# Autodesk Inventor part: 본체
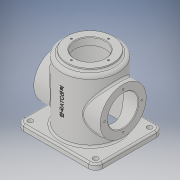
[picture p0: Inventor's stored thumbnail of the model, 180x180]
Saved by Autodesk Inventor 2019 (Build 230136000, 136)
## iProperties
Created: 2020-12
Part Number: 본체
Material: 일반
Document SubType Name: Modeling
Designer: jun-1-19
Density: 1 g/cm^3
Appearance: 기본값
Mass: 457.557 g
Surface Area: 1067.12 cm^2
Volume: 457.557 cm^3
Author: jun-1-19
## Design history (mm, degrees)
sketch "스케치1"
  geometry: L1 (70, -60)-(-70, -60); L2 (-70, -60)-(-70, 60); L3 (-70, 60)-(70, 60); L4 (70, 60)-(70, -60); L5 (70, -60)-(-70, 60); L6 (-70, -60)-(70, 60); 1 further point
  constraints: 12 end point, 2 midpoint, 2 parallel, 1 horizontal, 1 perpendicular
  dimensions: "d0" = 140 distance of L2.end L3.end; "d1" = 120 distance of L1.end L2.end
extrude "돌출1" new body sketch "스케치1" distance "d2" = 10; taper "d3" = 0 deg
sketch "스케치2"
  geometry: C1 r 50 at (0, 0); 1 further point
  constraints: 1 centre point, 1 coincident
  dimensions: "d4" = 100 diameter of C1
extrude "돌출2" join sketch "스케치2" distance "d5" = 110; taper "d6" = 0 deg
sketch "스케치4"
  geometry: C1 r 41 at (0, 0); 1 further point
  constraints: 1 centre point, 1 coincident
  dimensions: "d8" = 82 diameter of C1
extrude "돌출3" join sketch "스케치4" distance "d9" = 5; taper "d10" = 0 deg
sketch "스케치5"
  geometry: 3 further points
  constraints: 2 coincident
hole "구멍1" sketch "스케치5" at (0, 0) diameter "d11" = 54; stored, may be unused: countersink angle "d15" = 90 deg, drill point angle "d17" = 0 deg; dims "d12" = 18, "d13" = 84, "d14" = 112, "d16" = 23
node "작업 평면4"
sketch "스케치6"
  geometry: L1 (0, -60)-(0, 60) reference; C1 r 41 at (60, 0); 2 further points
  constraints: 1 centre point, 1 horizontal alignment, 1 midpoint
  dimensions: "d19" = 82 diameter of C1; "d20" = 60 distance from line of L1 C1.centre
extrude "돌출4" join sketch "스케치6" stored distance "d21" = 5; taper "d22" = 0 deg
sketch "스케치7"
  geometry: C1 r 41 at (0, 0) reference; 2 further points
  constraints: 1 coincident
hole "구멍2" sketch "스케치7" at (0, 0) diameter "d23" = 54; stored, may be unused: countersink angle "d27" = 90 deg, drill point angle "d29" = 0 deg; dims "d24" = 18, "d25" = 84, "d26" = 112, "d28" = 23
fillet "모깎기1" dims "d30" = 12
sketch "스케치8"
  geometry: A1 r 12 centre (58, -48) between (58, -60) and (70, -48) reference; 2 further points
  constraints: 1 coincident
hole "구멍3" sketch "스케치8" at (58, -48) diameter "d31" = 9; stored, may be unused: countersink angle "d35" = 90 deg, drill point angle "d37" = 0 deg; dims "d32" = 18, "d33" = 84, "d34" = 112, "d36" = 23
fillet "모깎기2" dims "d38" = 3
sketch "스케치9"
  geometry: 2 further points
  constraints: 1 vertical alignment
  dimensions: "d39" = 33 distance of point (0, 0) point (0, 33)
hole "구멍4" sketch "스케치9" at (0, 33) diameter "d40" = 3.242; stored, may be unused: countersink angle "d44" = 90 deg, drill point angle "d46" = 118 deg; dims "d41" = 8, "d42" = 84, "d43" = 112, "d45" = 10
sketch "스케치10"
  geometry: L1 (48, -60)-(-48, -60) reference; C1 r 41 at (0, 0) reference; 3 further points
  constraints: 1 midpoint, 1 vertical alignment
  dimensions: "d50" = 33 distance of C1.centre point (0, 33)
hole "구멍5" sketch "스케치10" at (0, 33) diameter "d51" = 3.242; stored, may be unused: countersink angle "d55" = 90 deg, drill point angle "d57" = 118 deg; dims "d52" = 8, "d53" = 84, "d54" = 112, "d56" = 10
fillet "모깎기3" dims "d61" = 3
chamfer "모따기1" distance "d62" = 1; stored, may be unused: second distance "d63" = 2, angle "d64" = 45 deg
chamfer "모따기2" distance "d65" = 1; stored, may be unused: second distance "d66" = 2, angle "d67" = 45 deg
node "작업 평면5"
sketch "스케치11"
  geometry: L1 (58, -10)-(-58, -10) reference; 3 further points
  constraints: 1 midpoint, 1 vertical alignment, 1 other
  dimensions: "d68" = 70 distance from line of L1 point (0, 60)
feature "엠보싱1" sketch "스케치11" dims "d0" = 140, "d1" = 120, "d14" = 112, "d69" = 0.5, "d70" = 0
fillet "모깎기4" dims "d71" = 6
fillet "모깎기5" dims "d72" = 3
node "솔리드1"
mirror "미러1"
mirror "미러2"
mirror "미러3"
pattern_circular "원형 패턴1" dims angle "d48" = 360 deg
pattern_circular "원형 패턴2" dims angle "d59" = 360 deg
mirror "미러4"
other parameters: "d18" = 59
